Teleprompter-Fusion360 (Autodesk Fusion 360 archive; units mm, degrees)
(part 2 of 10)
sketch "Skizze23" plane through (-14.9969, 0, 0) normal (-1, 0, 0) x axis (0, -1, 0)
  line L1 (18.6596, 263) -> (18.6596, 251.0692)
  line L2 (0.4576, 267) -> (14.6596, 267)
  line L3 (-121.7, 256.955) -> (-0.5298, 266.9593)
  line L4 (-126.9563, 256.521) -> (-123.6681, 256.7925)
  line L5 (-255.037, 12) -> (-136.7133, 249.9055)
  line L6 (-220.3404, 12) -> (-255.037, 12)
  line L7 (-169.9972, 16) -> (-214.6835, 16)
  line L8 (6.6596, 12) -> (-164.3404, 12)
  line L9 (6.6596, 15) -> (6.6596, 12)
  line L10 (-58.0916, 27) -> (-5.3404, 27)
  line L11 (-70.0916, 152.3769) -> (-70.0916, 39)
  line L12 (15.1449, 242.5839) -> (-66.5768, 160.8622)
  line L13 (-45.7711, 251.1832) -> (-86.6874, 247.805)
  line L14 (-77.2147, 189.8223) -> (-36.2984, 230.7386)
  line L15 (-97.7, 235.8456) -> (-97.7, 198.3075)
  line L16 (-94.0916, 39) -> (-94.0916, 104.3769)
  line L17 (-171.4684, 27) -> (-106.0916, 27)
  line L18 (-114.5768, 112.8622) -> (-179.9537, 47.4853)
  line L19 (-156.4445, 183.2864) -> (-195.6625, 104.4333)
  line L20 (-133.7, 138.3075) -> (-133.7, 177.9426)
  line L21 (-176.4327, 90.6042) -> (-137.2147, 129.8223)
  line L22 (-121.7, 244.955) -> (-121.7, 150.455)
  line L23 (-109.7, 244.955) -> (-121.7, 244.955)
  line L24 (-109.7, 150.455) -> (-109.7, 244.955)
  line L25 (-121.7, 150.455) -> (-109.7, 150.455)
  line L26 (-109.7, 213.455) -> (-121.7, 213.455)
  line L27 (-109.7, 181.955) -> (-121.7, 181.955)
  line L28 (-119.5787, 242.8337) -> (-121.7, 244.955)
  line L29 (-113.5498, 244.955) -> (-117.4574, 244.955)
  line L30 (-111.8213, 242.8337) -> (-109.7, 244.955)
  line L31 (-103.0112, 244.955) -> (-109.7, 244.955)
  line L32 (-113.9426, 244.955) -> (-121.7, 244.955)
  line L33 (-109.7, 213.455) -> (-109.7, 240.7124)
  line L34 (-117.4574, 213.455) -> (-109.7, 213.455)
  line L35 (-121.7, 240.7124) -> (-121.7, 213.455)
  line L36 (-119.5787, 215.5763) -> (-121.7, 213.455)
  line L37 (-118.7, 213.455) -> (-121.7, 213.455)
  line L38 (-111.8213, 215.5763) -> (-109.7, 213.455)
  line L39 (-106.7, 213.455) -> (-109.7, 213.455)
  arc A1 centre (6.6596, 251.0692) radius 12 clockwise from (18.6596, 251.0692) to (15.1449, 242.5839)
  arc A2 centre (14.6596, 263) radius 4 clockwise from (14.6596, 267) to (18.6596, 263)
  arc A3 centre (0.4576, 255) radius 12 clockwise from (-0.5298, 266.9593) to (0.4576, 267)
  arc A4 centre (-121.7, 244.955) radius 12 clockwise from (-123.6681, 256.7925) to (-121.7, 256.955)
  arc A5 centre (-125.9689, 244.5617) radius 12 clockwise from (-136.7133, 249.9055) to (-126.9563, 256.521)
  arc A6 centre (-214.6835, 10) radius 6 clockwise from (-220.3404, 12) to (-214.6835, 16)
  arc A7 centre (-169.9972, 10) radius 6 clockwise from (-169.9972, 16) to (-164.3404, 12)
  arc A8 centre (-5.3404, 15) radius 12 clockwise from (-5.3404, 27) to (6.6596, 15)
  arc A9 centre (-58.0916, 39) radius 12 clockwise from (-58.0916, 27) to (-70.0916, 39)
  arc A10 centre (-58.0916, 152.3769) radius 12 clockwise from (-70.0916, 152.3769) to (-66.5768, 160.8622)
  arc A11 centre (-85.7, 235.8456) radius 12 clockwise from (-97.7, 235.8456) to (-86.6874, 247.805)
  arc A12 centre (-44.7837, 239.2239) radius 12 clockwise from (-45.7711, 251.1832) to (-36.2984, 230.7386)
  arc A13 centre (-85.7, 198.3075) radius 12 clockwise from (-77.2147, 189.8223) to (-97.7, 198.3075)
  arc A14 centre (-106.0916, 39) radius 12 clockwise from (-94.0916, 39) to (-106.0916, 27)
  arc A15 centre (-171.4684, 39) radius 12 clockwise from (-171.4684, 27) to (-179.9537, 47.4853)
  arc A16 centre (-106.0916, 104.3769) radius 12 clockwise from (-114.5768, 112.8622) to (-94.0916, 104.3769)
  arc A17 centre (-184.918, 99.0895) radius 12 clockwise from (-176.4327, 90.6042) to (-195.6625, 104.4333)
  arc A18 centre (-145.7, 177.9426) radius 12 clockwise from (-156.4445, 183.2864) to (-133.7, 177.9426)
  arc A19 centre (-145.7, 138.3075) radius 12 clockwise from (-133.7, 138.3075) to (-137.2147, 129.8223)
  arc A20 centre (-119.5787, 242.8337) radius 3 clockwise from (-121.7, 240.7124) to (-117.4574, 244.955)
  arc A21 centre (-111.8213, 242.8337) radius 3 clockwise from (-113.9426, 244.955) to (-109.7, 240.7124)
  arc A22 centre (-119.5787, 215.5763) radius 3 clockwise from (-117.4574, 213.455) to (-121.7, 217.6976)
  arc A23 centre (-111.8213, 215.5763) radius 3 clockwise from (-109.7, 217.6976) to (-113.9426, 213.455)
  arc A24 centre (-119.5787, 179.8337) radius 3 clockwise from (-121.7, 177.7124) to (-117.4574, 181.955)
  arc A25 centre (-111.8213, 179.8337) radius 3 clockwise from (-113.9426, 181.955) to (-109.7, 177.7124)
  arc A26 centre (-111.8213, 152.5763) radius 3 clockwise from (-109.7, 154.6976) to (-113.9426, 150.455)
  arc A27 centre (-119.5787, 152.5763) radius 3 clockwise from (-117.4574, 150.455) to (-121.7, 154.6976)
  point P65 (-121.7, 213.455)
  point P66 (-109.7, 213.455)
  point P67 (-121.7, 181.955)
  point P68 (-109.7, 181.955)
  point P62 (-121.7, 244.955)
  point P69 (-121.7, 244.955)
  point P63 (-109.7, 244.955)
  point P72 (-109.7, 244.955)
  point P70 (-119.5787, 242.8337)
  point P75 (-119.5787, 242.8337)
  point P73 (-111.8213, 242.8337)
  point P76 (-111.8213, 242.8337)
  point P77 (-121.7, 240.7124)
  point P78 (-117.4574, 244.955)
  point P79 (-113.9426, 244.955)
  point P80 (-109.7, 240.7124)
  point P82 (-119.5787, 215.5763)
  point P86 (-119.5787, 215.5763)
  point P84 (-111.8213, 215.5763)
  point P87 (-111.8213, 215.5763)
  point P88 (-117.4574, 213.455)
  point P89 (-121.7, 217.6976)
  point P90 (-109.7, 217.6976)
  point P91 (-113.9426, 213.455)
  coincident L22 P65
  coincident L24 P66
  perpendicular L24 L26
  coincident L22 P67
  coincident L24 P68
  perpendicular L24 L27
  horizontal L29
  coincident P62 P69
  horizontal L31
  coincident P63 P72
  coincident P70 P75
  coincident P62 A20
  coincident P73 P76
  coincident P72 A21
  coincident L22 P77
  coincident L23 P78
  coincident L23 P79
  coincident L24 P80
  horizontal L32
  vertical L33
  horizontal L34
  vertical L35
  horizontal L37
  horizontal L39
  coincident P82 P86
  coincident P65 A22
  coincident P84 P87
  coincident P66 A23
  coincident L26 P88
  coincident L22 P89
  coincident L24 P90
  coincident L26 P91
  dimension "d154" distance L23 L25 = 94.5
  dimension "d155" distance L23 L26 = 31.5 (= "94.50 mm / 3")
  dimension "d156" distance L25 L27 = 31.5 (= "d155")
  dimension "d157" angle L28 L29 = 45
  dimension "d158" angle L30 L31 = 135
  dimension "d159" distance P69 P70 = 3
  dimension "d160" distance P72 P73 = 3
  dimension "d161" angle L36 L37 = 45
  dimension "d162" distance P65 P82 = 3
  dimension "d163" angle L38 L39 = 135
  dimension "d164" distance P66 P84 = 3
extrude "Extrusion21" cut sketch "Skizze23" profile of L22 L23 L24 L25 L26 L27 A20 A21 L32 L33 L34 L35 A22 A23 A24 A25 A26 A27 against normal blind 12
sketch "Skizze24" plane through (-2.9969, 0, 0) normal (-1, 0, 0) x axis (0, -1, 0)
  line L1 (-121.7, 150.455) -> (-121.7, 244.955)
  line L2 (-109.7, 150.455) -> (-121.7, 150.455)
  line L3 (-109.7, 244.955) -> (-109.7, 150.455)
  line L4 (-121.7, 244.955) -> (-109.7, 244.955)
  line L5 (-117.4574, 213.455) -> (-113.9426, 213.455)
  line L6 (-113.9426, 181.955) -> (-117.4574, 181.955)
  line L7 (-109.7, 213.455) -> (-121.7, 213.455)
  line L8 (-109.7, 181.955) -> (-121.7, 181.955)
  line L9 (-109.7, 244.955) -> (-121.7, 244.955)
  line L10 (-109.7, 150.455) -> (-109.7, 244.955)
  line L11 (-121.7, 150.455) -> (-109.7, 150.455)
  line L12 (-121.7, 244.955) -> (-121.7, 150.455)
  line L13 (-57.478, 225.7975) -> (-82.6117, 225.7975)
  line L14 (-57.478, 237.011) -> (-57.478, 225.7975)
  line L15 (-82.6117, 237.011) -> (-57.478, 237.011)
  line L16 (-82.6117, 225.7975) -> (-82.6117, 237.011)
  point P10 (-121.7, 213.455)
  point P11 (-109.7, 213.455)
  point P12 (-121.7, 181.955)
  point P13 (-109.7, 181.955)
  point P4 (-109.7, 150.455)
  point P16 (-109.7, 150.455)
  point P2 (-121.7, 244.955)
  point P14 (-121.7, 244.955)
  coincident L1 P10
  coincident L3 P11
  perpendicular L3 L7
  coincident L1 P12
  coincident L3 P13
  perpendicular L1 L8
  horizontal L9
  vertical L10
  horizontal L11
  vertical L12
  coincident P4 P16
  coincident P2 P14
  horizontal L13
  vertical L14
  horizontal L15
  vertical L16
extrude "Extrusion22" add sketch "Skizze24" profile of L1 L2 L3 L4 L5 L6 L7 L8 L9 L10 L11 L12 along normal blind 12
sketch "Skizze25" plane through (0, 121.7, 0) normal (0, 1, 0) x axis (-1, 0, 0)
  line L1 (-161.0025, 189.955) -> (-161.0025, 194.455)
  line L2 (-141.7525, 189.955) -> (-161.0025, 189.955)
  line L3 (-217.2525, 162.455) -> (-141.7525, 162.455)
  line L4 (-198.0025, 189.955) -> (-217.2525, 189.955)
  line L5 (-198.0025, 194.455) -> (-198.0025, 189.955)
  line L6 (-165.0025, 198.455) -> (-194.0025, 198.455)
  line L7 (-98.617, 174.455) -> (-33.0031, 174.455)
  line L8 (-141.6023, 212.4697) -> (-107.1023, 177.9697)
  line L9 (-33.0031, 232.955) -> (-133.117, 232.955)
  line L10 (-21.0031, 186.455) -> (-21.0031, 220.955)
  line L11 (-338.0031, 220.955) -> (-338.0031, 186.455)
  line L12 (-225.8891, 232.955) -> (-326.0031, 232.955)
  line L13 (-251.9038, 177.9697) -> (-217.4038, 212.4697)
  line L14 (-326.0031, 174.455) -> (-260.3891, 174.455)
  line L15 (14.9969, 150.455) -> (-362.0031, 150.455)
  line L16 (14.9969, 181.955) -> (14.9969, 150.455)
  line L17 (2.9969, 181.955) -> (14.9969, 181.955)
  line L18 (2.9969, 213.455) -> (2.9969, 181.955)
  line L19 (14.9969, 213.455) -> (2.9969, 213.455)
  line L20 (14.9969, 244.955) -> (14.9969, 213.455)
  line L21 (-362.0031, 244.955) -> (14.9969, 244.955)
  line L22 (-362.0031, 150.455) -> (-362.0031, 244.955)
  line L23 (5.1183, 211.3337) -> (2.9969, 213.455)
  line L24 (5.9969, 213.455) -> (2.9969, 213.455)
  line L25 (5.1183, 184.0763) -> (2.9969, 181.955)
  line L26 (5.9969, 181.955) -> (2.9969, 181.955)
  arc A1 centre (-141.7525, 176.205) radius 13.75 clockwise from (-141.7525, 189.955) to (-141.7525, 162.455)
  arc A2 centre (-217.2525, 176.205) radius 13.75 clockwise from (-217.2525, 162.455) to (-217.2525, 189.955)
  arc A3 centre (-194.0025, 194.455) radius 4 clockwise from (-198.0025, 194.455) to (-194.0025, 198.455)
  arc A4 centre (-165.0025, 194.455) radius 4 clockwise from (-165.0025, 198.455) to (-161.0025, 194.455)
  arc A5 centre (-98.617, 186.455) radius 12 clockwise from (-98.617, 174.455) to (-107.1023, 177.9697)
  arc A6 centre (-133.117, 220.955) radius 12 clockwise from (-141.6023, 212.4697) to (-133.117, 232.955)
  arc A7 centre (-33.0031, 220.955) radius 12 clockwise from (-33.0031, 232.955) to (-21.0031, 220.955)
  arc A8 centre (-33.0031, 186.455) radius 12 clockwise from (-21.0031, 186.455) to (-33.0031, 174.455)
  arc A9 centre (-326.0031, 220.955) radius 12 clockwise from (-338.0031, 220.955) to (-326.0031, 232.955)
  arc A10 centre (-225.8891, 220.955) radius 12 clockwise from (-225.8891, 232.955) to (-217.4038, 212.4697)
  arc A11 centre (-260.3891, 186.455) radius 12 clockwise from (-251.9038, 177.9697) to (-260.3891, 174.455)
  arc A12 centre (-326.0031, 186.455) radius 12 clockwise from (-326.0031, 174.455) to (-338.0031, 186.455)
  circle C1 centre (5.1183, 184.0763) radius 3
  circle C2 centre (5.1183, 211.3337) radius 3
  point P44 (2.9969, 213.455)
  point P48 (2.9969, 213.455)
  point P43 (2.9969, 181.955)
  point P51 (2.9969, 181.955)
  point P52 (5.1183, 184.0763)
  point P54 (5.1183, 184.0763)
  point P49 (5.1183, 211.3337)
  point P55 (5.1183, 211.3337)
  horizontal L24
  coincident P44 P48
  horizontal L26
  coincident P43 P51
  coincident P52 P54
  coincident P43 C1
  coincident P49 P55
  coincident P44 C2
  dimension "d169" angle L23 L24 = 45
  dimension "d170" distance P48 P49 = 3
  dimension "d171" angle L25 L26 = 45
  dimension "d172" distance P51 P52 = 3
extrude "Extrusion23" cut sketch "Skizze25" profile of L17 L18 L19 C1 C2 against normal blind 12
work_plane "Arbeitsebene3"
mirror "Spiegeln1" mirrorStitchTolerance 0.1
sketch "Skizze26" plane through (362.0031, 0, 0) normal (1, 0, 0) x axis (0, 1, 0)
  line L1 (121.7, 213.455) -> (109.7, 213.455)
  line L2 (121.7, 244.955) -> (121.7, 213.455)
  line L3 (109.7, 244.955) -> (121.7, 244.955)
  line L4 (109.7, 213.455) -> (109.7, 244.955)
  line L5 (121.7, 213.455) -> (121.7, 244.955)
  line L6 (109.7, 213.455) -> (121.7, 213.455)
  line L7 (109.7, 244.955) -> (109.7, 213.455)
  line L8 (121.7, 244.955) -> (109.7, 244.955)
  line L9 (109.7, 150.455) -> (121.7, 150.455)
  line L10 (109.7, 181.955) -> (109.7, 150.455)
  line L11 (121.7, 181.955) -> (109.7, 181.955)
  line L12 (121.7, 150.455) -> (121.7, 181.955)
extrude "Extrusion24" add sketch "Skizze26" along normal blind 12
sketch "Skizze27" plane through (0, 121.7, 0) normal (0, 1, 0) x axis (-1, 0, 0)
  line L1 (-338.0031, 220.955) -> (-338.0031, 186.455)
  line L2 (-225.8891, 232.955) -> (-326.0031, 232.955)
  line L3 (-251.9038, 177.9697) -> (-217.4038, 212.4697)
  line L4 (-326.0031, 174.455) -> (-260.3891, 174.455)
  line L5 (-98.617, 174.455) -> (-33.0031, 174.455)
  line L6 (-141.6023, 212.4697) -> (-107.1023, 177.9697)
  line L7 (-33.0031, 232.955) -> (-133.117, 232.955)
  line L8 (-21.0031, 186.455) -> (-21.0031, 220.955)
  line L9 (-161.0025, 189.955) -> (-161.0025, 194.455)
  line L10 (-141.7525, 189.955) -> (-161.0025, 189.955)
  line L11 (-217.2525, 162.455) -> (-141.7525, 162.455)
  line L12 (-198.0025, 189.955) -> (-217.2525, 189.955)
  line L13 (-198.0025, 194.455) -> (-198.0025, 189.955)
  line L14 (-165.0025, 198.455) -> (-194.0025, 198.455)
  line L15 (-362.0031, 186.1976) -> (-362.0031, 209.2124)
  line L16 (-374.0031, 181.955) -> (-362.0031, 181.955)
  line L17 (-374.0031, 150.455) -> (-374.0031, 181.955)
  line L18 (14.9969, 150.455) -> (-374.0031, 150.455)
  line L19 (14.9969, 181.955) -> (14.9969, 150.455)
  line L20 (7.2396, 181.955) -> (14.9969, 181.955)
  line L21 (2.9969, 209.2124) -> (2.9969, 186.1976)
  line L22 (14.9969, 213.455) -> (7.2396, 213.455)
  line L23 (14.9969, 244.955) -> (14.9969, 213.455)
  line L24 (-374.0031, 244.955) -> (14.9969, 244.955)
  line L25 (-374.0031, 213.455) -> (-374.0031, 244.955)
  line L26 (-362.0031, 213.455) -> (-374.0031, 213.455)
  arc A1 centre (-326.0031, 220.955) radius 12 clockwise from (-338.0031, 220.955) to (-326.0031, 232.955)
  arc A2 centre (-225.8891, 220.955) radius 12 clockwise from (-225.8891, 232.955) to (-217.4038, 212.4697)
  arc A3 centre (-260.3891, 186.455) radius 12 clockwise from (-251.9038, 177.9697) to (-260.3891, 174.455)
  arc A4 centre (-326.0031, 186.455) radius 12 clockwise from (-326.0031, 174.455) to (-338.0031, 186.455)
  arc A5 centre (-98.617, 186.455) radius 12 clockwise from (-98.617, 174.455) to (-107.1023, 177.9697)
  arc A6 centre (-133.117, 220.955) radius 12 clockwise from (-141.6023, 212.4697) to (-133.117, 232.955)
  arc A7 centre (-33.0031, 220.955) radius 12 clockwise from (-33.0031, 232.955) to (-21.0031, 220.955)
  arc A8 centre (-33.0031, 186.455) radius 12 clockwise from (-21.0031, 186.455) to (-33.0031, 174.455)
  arc A9 centre (-141.7525, 176.205) radius 13.75 clockwise from (-141.7525, 189.955) to (-141.7525, 162.455)
  arc A10 centre (-217.2525, 176.205) radius 13.75 clockwise from (-217.2525, 162.455) to (-217.2525, 189.955)
  arc A11 centre (-194.0025, 194.455) radius 4 clockwise from (-198.0025, 194.455) to (-194.0025, 198.455)
  arc A12 centre (-165.0025, 194.455) radius 4 clockwise from (-165.0025, 198.455) to (-161.0025, 194.455)
  arc A13 centre (-364.1244, 211.3337) radius 3 clockwise from (-362.0031, 213.455) to (-362.0031, 209.2124)
  arc A14 centre (-364.1244, 184.0763) radius 3 clockwise from (-362.0031, 186.1976) to (-362.0031, 181.955)
  arc A15 centre (5.1183, 184.0763) radius 3 clockwise from (7.2396, 181.955) to (2.9969, 186.1976)
  arc A16 centre (5.1183, 211.3337) radius 3 clockwise from (2.9969, 209.2124) to (7.2396, 213.455)
  circle C1 centre (-364.1244, 211.3337) radius 3
  circle C2 centre (-364.1244, 184.0763) radius 3
  point P40 (-362.0031, 209.2124)
  point P41 (-362.0031, 213.455)
  point P43 (-362.0031, 186.1976)
  point P44 (-362.0031, 181.955)
  coincident P40 C1
  coincident P41 C1
  coincident P43 C2
  coincident P44 C2
extrude "Extrusion25" cut sketch "Skizze27" profile of L16 L26 C1 C2 against normal blind 12
offset_faces "Flächen versetzen2" distance 12
sketch "Skizze28" plane through (-14.9969, 0, 0) normal (-1, 0, 0) x axis (0, -1, 0)
  line L1 (-114.5768, 112.8622) -> (-167.9537, 59.4853)
  line L2 (-94.0916, 51) -> (-94.0916, 104.3769)
  line L3 (-159.4684, 39) -> (-106.0916, 39)
  line L4 (-169.9972, 16) -> (-214.6835, 16)
  line L5 (6.6596, 12) -> (-164.3404, 12)
  line L6 (6.6596, 15) -> (6.6596, 12)
  line L7 (-58.0916, 27) -> (-5.3404, 27)
  line L8 (-70.0916, 152.3769) -> (-70.0916, 39)
  line L9 (15.1449, 242.5839) -> (-66.5768, 160.8622)
  line L10 (18.6596, 263) -> (18.6596, 251.0692)
  line L11 (0.4576, 267) -> (14.6596, 267)
  line L12 (-121.7, 256.955) -> (-0.5298, 266.9593)
  line L13 (-126.9563, 256.521) -> (-123.6681, 256.7925)
  line L14 (-255.037, 12) -> (-136.7133, 249.9055)
  line L15 (-220.3404, 12) -> (-255.037, 12)
  line L16 (-121.7, 177.7124) -> (-121.7, 154.6976)
  line L17 (-113.9426, 181.955) -> (-117.4574, 181.955)
  line L18 (-109.7, 154.6976) -> (-109.7, 177.7124)
  line L19 (-117.4574, 150.455) -> (-113.9426, 150.455)
  line L20 (-117.4574, 213.455) -> (-113.9426, 213.455)
  line L21 (-121.7, 240.7124) -> (-121.7, 217.6976)
  line L22 (-113.9426, 244.955) -> (-117.4574, 244.955)
  line L23 (-109.7, 217.6976) -> (-109.7, 240.7124)
  line L24 (-45.7711, 251.1832) -> (-86.6874, 247.805)
  line L25 (-77.2147, 189.8223) -> (-36.2984, 230.7386)
  line L26 (-97.7, 235.8456) -> (-97.7, 198.3075)
  line L27 (-156.4445, 183.2864) -> (-195.6625, 104.4333)
  line L28 (-133.7, 138.3075) -> (-133.7, 177.9426)
  line L29 (-176.4327, 90.6042) -> (-137.2147, 129.8223)
  line L30 (6.6596, 12) -> (6.6596, 0)
  line L31 (-164.3404, 12) -> (6.6596, 12)
  line L32 (-164.3404, 4) -> (-164.3404, 12)
  line L33 (-220.3404, 4) -> (-164.3404, 4)
  line L34 (-220.3404, 12) -> (-220.3404, 4)
  line L35 (-232.4096, 12) -> (-220.3404, 12)
  line L36 (-232.4096, 7.0503) -> (-232.4096, 12)
  line L37 (-240.1877, 7.0503) -> (-232.4096, 7.0503)
  line L38 (-240.1877, 12) -> (-240.1877, 7.0503)
  line L39 (-255.3404, 12) -> (-240.1877, 12)
  line L40 (-255.3404, 0) -> (-255.3404, 12)
  line L41 (6.6596, 0) -> (-255.3404, 0)
  line L42 (-164.3404, 0) -> (-164.3404, 12)
  line L43 (6.6596, 0) -> (6.6596, 12)
  line L44 (-130.1404, 0) -> (-130.1404, 12)
  line L45 (-95.9404, 0) -> (-95.9404, 12)
  line L46 (-61.7404, 0) -> (-61.7404, 12)
  line L47 (-27.5404, 0) -> (-27.5404, 12)
  arc A1 centre (-106.0916, 104.3769) radius 12 clockwise from (-114.5768, 112.8622) to (-94.0916, 104.3769)
  arc A2 centre (-106.0916, 51) radius 12 clockwise from (-94.0916, 51) to (-106.0916, 39)
  arc A3 centre (-159.4684, 51) radius 12 clockwise from (-159.4684, 39) to (-167.9537, 59.4853)
  arc A4 centre (-169.9972, 10) radius 6 clockwise from (-169.9972, 16) to (-164.3404, 12)
  arc A5 centre (-5.3404, 15) radius 12 clockwise from (-5.3404, 27) to (6.6596, 15)
  arc A6 centre (-58.0916, 39) radius 12 clockwise from (-58.0916, 27) to (-70.0916, 39)
  arc A7 centre (-58.0916, 152.3769) radius 12 clockwise from (-70.0916, 152.3769) to (-66.5768, 160.8622)
  arc A8 centre (6.6596, 251.0692) radius 12 clockwise from (18.6596, 251.0692) to (15.1449, 242.5839)
  arc A9 centre (14.6596, 263) radius 4 clockwise from (14.6596, 267) to (18.6596, 263)
  arc A10 centre (0.4576, 255) radius 12 clockwise from (-0.5298, 266.9593) to (0.4576, 267)
  arc A11 centre (-121.7, 244.955) radius 12 clockwise from (-123.6681, 256.7925) to (-121.7, 256.955)
  arc A12 centre (-125.9689, 244.5617) radius 12 clockwise from (-136.7133, 249.9055) to (-126.9563, 256.521)
  arc A13 centre (-214.6835, 10) radius 6 clockwise from (-220.3404, 12) to (-214.6835, 16)
  arc A14 centre (-119.5787, 179.8337) radius 3 clockwise from (-121.7, 177.7124) to (-117.4574, 181.955)
  arc A15 centre (-111.8213, 179.8337) radius 3 clockwise from (-113.9426, 181.955) to (-109.7, 177.7124)
  arc A16 centre (-111.8213, 152.5763) radius 3 clockwise from (-109.7, 154.6976) to (-113.9426, 150.455)
  arc A17 centre (-119.5787, 152.5763) radius 3 clockwise from (-117.4574, 150.455) to (-121.7, 154.6976)
  arc A18 centre (-119.5787, 215.5763) radius 3 clockwise from (-117.4574, 213.455) to (-121.7, 217.6976)
  arc A19 centre (-119.5787, 242.8337) radius 3 clockwise from (-121.7, 240.7124) to (-117.4574, 244.955)
  arc A20 centre (-111.8213, 242.8337) radius 3 clockwise from (-113.9426, 244.955) to (-109.7, 240.7124)
  arc A21 centre (-111.8213, 215.5763) radius 3 clockwise from (-109.7, 217.6976) to (-113.9426, 213.455)
  arc A22 centre (-85.7, 235.8456) radius 12 clockwise from (-97.7, 235.8456) to (-86.6874, 247.805)
  arc A23 centre (-44.7837, 239.2239) radius 12 clockwise from (-45.7711, 251.1832) to (-36.2984, 230.7386)
  arc A24 centre (-85.7, 198.3075) radius 12 clockwise from (-77.2147, 189.8223) to (-97.7, 198.3075)
  arc A25 centre (-184.918, 99.0895) radius 12 clockwise from (-176.4327, 90.6042) to (-195.6625, 104.4333)
  arc A26 centre (-145.7, 177.9426) radius 12 clockwise from (-156.4445, 183.2864) to (-133.7, 177.9426)
  arc A27 centre (-145.7, 138.3075) radius 12 clockwise from (-133.7, 138.3075) to (-137.2147, 129.8223)
  point P87 (-164.3404, 12)
  point P97 (-164.3404, 12)
  point P98 (-164.3404, 0)
  point P86 (6.6596, 12)
  point P99 (6.6596, 12)
  point P85 (6.6596, 0)
  point P100 (6.6596, 0)
  point P101 (-130.1404, 12)
  point P102 (-130.1404, 0)
  point P103 (-95.9404, 12)
  point P104 (-95.9404, 0)
  point P105 (-61.7404, 12)
  point P106 (-61.7404, 0)
  point P107 (-27.5404, 12)
  point P108 (-27.5404, 0)
  coincident P87 P97
  coincident L41 P98
  perpendicular L41 L42
  coincident P86 P99
  coincident P85 P100
  coincident L31 P101
  coincident L41 P102
  perpendicular L41 L44
  coincident L31 P103
  coincident L41 P104
  perpendicular L41 L45
  coincident L31 P105
  coincident L41 P106
  perpendicular L41 L46
  coincident L5 P107
  coincident L41 P108
  perpendicular L41 L47
  dimension "d182" distance L42 L44 = 34.2 (= "( 171 / 5 ) * 1 mm")
  dimension "d183" distance L44 L45 = 34.2 (= "d182")
  dimension "d184" distance L45 L46 = 34.2 (= "d183")
  dimension "d185" distance L46 L47 = 34.2 (= "d184")
  dimension "d186" distance L43 L47 = 34.2
extrude "Extrusion26" add sketch "Skizze28" profile of L5 L30 L31 L32 L41 L42 L43 L44 L45 L46 L47 against normal blind 12
sketch "Skizze29" plane through (-14.9969, 0, 0) normal (-1, 0, 0) x axis (0, -1, 0)
  line L1 (-114.5768, 112.8622) -> (-167.9537, 59.4853)
  line L2 (-94.0916, 51) -> (-94.0916, 104.3769)
  line L3 (-159.4684, 39) -> (-106.0916, 39)
  line L4 (-169.9972, 16) -> (-214.6835, 16)
  line L5 (-164.3404, 0) -> (-164.3404, 12)
  line L6 (-130.1404, 0) -> (-164.3404, 0)
  line L7 (-130.1404, 12) -> (-130.1404, 0)
  line L8 (-95.9404, 12) -> (-130.1404, 12)
  line L9 (-95.9404, 0) -> (-95.9404, 12)
  line L10 (-61.7404, 0) -> (-95.9404, 0)
  line L11 (-61.7404, 12) -> (-61.7404, 0)
  line L12 (-27.5404, 12) -> (-61.7404, 12)
  line L13 (-27.5404, 0) -> (-27.5404, 12)
  line L14 (6.6596, 0) -> (-27.5404, 0)
  line L15 (6.6596, 15) -> (6.6596, 0)
  line L16 (-58.0916, 27) -> (-5.3404, 27)
  line L17 (-70.0916, 152.3769) -> (-70.0916, 39)
  line L18 (15.1449, 242.5839) -> (-66.5768, 160.8622)
  line L19 (18.6596, 263) -> (18.6596, 251.0692)
  line L20 (0.4576, 267) -> (14.6596, 267)
  line L21 (-121.7, 256.955) -> (-0.5298, 266.9593)
  line L22 (-126.9563, 256.521) -> (-123.6681, 256.7925)
  line L23 (-255.037, 12) -> (-136.7133, 249.9055)
  line L24 (-220.3404, 12) -> (-255.037, 12)
  line L25 (-121.7, 177.7124) -> (-121.7, 154.6976)
  line L26 (-113.9426, 181.955) -> (-117.4574, 181.955)
  line L27 (-109.7, 154.6976) -> (-109.7, 177.7124)
  line L28 (-117.4574, 150.455) -> (-113.9426, 150.455)
  line L29 (-117.4574, 213.455) -> (-113.9426, 213.455)
  line L30 (-121.7, 240.7124) -> (-121.7, 217.6976)
  line L31 (-113.9426, 244.955) -> (-117.4574, 244.955)
  line L32 (-109.7, 217.6976) -> (-109.7, 240.7124)
  line L33 (-45.7711, 251.1832) -> (-86.6874, 247.805)
  line L34 (-77.2147, 189.8223) -> (-36.2984, 230.7386)
  line L35 (-97.7, 235.8456) -> (-97.7, 198.3075)
  line L36 (-156.4445, 183.2864) -> (-195.6625, 104.4333)
  line L37 (-133.7, 138.3075) -> (-133.7, 177.9426)
  line L38 (-176.4327, 90.6042) -> (-137.2147, 129.8223)
  line L39 (6.6596, 12) -> (6.6596, 0)
  line L40 (-164.3404, 12) -> (6.6596, 12)
  line L41 (-164.3404, 4) -> (-164.3404, 12)
  line L42 (-220.3404, 4) -> (-164.3404, 4)
  line L43 (-220.3404, 12) -> (-220.3404, 4)
  line L44 (-232.4096, 12) -> (-220.3404, 12)
  line L45 (-232.4096, 7.0503) -> (-232.4096, 12)
  line L46 (-240.1877, 7.0503) -> (-232.4096, 7.0503)
  line L47 (-240.1877, 12) -> (-240.1877, 7.0503)
  line L48 (-255.3404, 12) -> (-240.1877, 12)
  line L49 (-255.3404, 0) -> (-255.3404, 12)
  line L50 (6.6596, 0) -> (-255.3404, 0)
  line L51 (-220.3404, 0) -> (-220.3404, 12)
  line L52 (-220.3404, 12) -> (-240.1877, 12)
  line L53 (-220.3404, 0) -> (-220.3404, 12)
  line L54 (-240.1877, 0) -> (-220.3404, 0)
  line L55 (-240.1877, 12) -> (-240.1877, 0)
  arc A1 centre (-106.0916, 104.3769) radius 12 clockwise from (-114.5768, 112.8622) to (-94.0916, 104.3769)
  arc A2 centre (-106.0916, 51) radius 12 clockwise from (-94.0916, 51) to (-106.0916, 39)
  arc A3 centre (-159.4684, 51) radius 12 clockwise from (-159.4684, 39) to (-167.9537, 59.4853)
  arc A4 centre (-169.9972, 10) radius 6 clockwise from (-169.9972, 16) to (-164.3404, 12)
  arc A5 centre (-5.3404, 15) radius 12 clockwise from (-5.3404, 27) to (6.6596, 15)
  arc A6 centre (-58.0916, 39) radius 12 clockwise from (-58.0916, 27) to (-70.0916, 39)
  arc A7 centre (-58.0916, 152.3769) radius 12 clockwise from (-70.0916, 152.3769) to (-66.5768, 160.8622)
  arc A8 centre (6.6596, 251.0692) radius 12 clockwise from (18.6596, 251.0692) to (15.1449, 242.5839)
  arc A9 centre (14.6596, 263) radius 4 clockwise from (14.6596, 267) to (18.6596, 263)
  arc A10 centre (0.4576, 255) radius 12 clockwise from (-0.5298, 266.9593) to (0.4576, 267)
  arc A11 centre (-121.7, 244.955) radius 12 clockwise from (-123.6681, 256.7925) to (-121.7, 256.955)
  arc A12 centre (-125.9689, 244.5617) radius 12 clockwise from (-136.7133, 249.9055) to (-126.9563, 256.521)
  arc A13 centre (-214.6835, 10) radius 6 clockwise from (-220.3404, 12) to (-214.6835, 16)
  arc A14 centre (-119.5787, 179.8337) radius 3 clockwise from (-121.7, 177.7124) to (-117.4574, 181.955)
  arc A15 centre (-111.8213, 179.8337) radius 3 clockwise from (-113.9426, 181.955) to (-109.7, 177.7124)
  arc A16 centre (-111.8213, 152.5763) radius 3 clockwise from (-109.7, 154.6976) to (-113.9426, 150.455)
  arc A17 centre (-119.5787, 152.5763) radius 3 clockwise from (-117.4574, 150.455) to (-121.7, 154.6976)
  arc A18 centre (-119.5787, 215.5763) radius 3 clockwise from (-117.4574, 213.455) to (-121.7, 217.6976)
  arc A19 centre (-119.5787, 242.8337) radius 3 clockwise from (-121.7, 240.7124) to (-117.4574, 244.955)
  arc A20 centre (-111.8213, 242.8337) radius 3 clockwise from (-113.9426, 244.955) to (-109.7, 240.7124)
  arc A21 centre (-111.8213, 215.5763) radius 3 clockwise from (-109.7, 217.6976) to (-113.9426, 213.455)
  arc A22 centre (-85.7, 235.8456) radius 12 clockwise from (-97.7, 235.8456) to (-86.6874, 247.805)
  arc A23 centre (-44.7837, 239.2239) radius 12 clockwise from (-45.7711, 251.1832) to (-36.2984, 230.7386)
  arc A24 centre (-85.7, 198.3075) radius 12 clockwise from (-77.2147, 189.8223) to (-97.7, 198.3075)
  arc A25 centre (-184.918, 99.0895) radius 12 clockwise from (-176.4327, 90.6042) to (-195.6625, 104.4333)
  arc A26 centre (-145.7, 177.9426) radius 12 clockwise from (-156.4445, 183.2864) to (-133.7, 177.9426)
  arc A27 centre (-145.7, 138.3075) radius 12 clockwise from (-133.7, 138.3075) to (-137.2147, 129.8223)
  point P99 (-220.3404, 12)
  point P106 (-220.3404, 12)
  point P107 (-220.3404, 0)
  point P103 (-240.1877, 12)
  point P108 (-240.1877, 12)
  coincident P99 P106
  coincident L50 P107
  perpendicular L50 L51
  horizontal L52
  vertical L53
  horizontal L54
  vertical L55
  coincident P103 P108
extrude "Extrusion27" add sketch "Skizze29" profile of L24 L43 L44 L45 L46 L47 L50 L51 L52 L53 L54 L55 against normal blind 12
sketch "Skizze30" plane through (-7.3469, 0, 0) normal (1, 0, 0) x axis (0, 1, 0)
  line L1 (-18.6596, 262.7863) -> (-18.6596, 263)
  line L2 (232.1267, 12) -> (-18.6596, 262.7863)
  line L3 (238.3493, 12) -> (232.1267, 12)
  line L4 (-16.2993, 266.6485) -> (238.3493, 12)
  line L5 (242.8632, 1.2635) -> (232.1267, 12)
  line L6 (242.8632, 7.486) -> (238.3493, 12)
  line L7 (242.8632, 1.2635) -> (242.8632, 7.486)
  arc A1 centre (-14.6596, 263) radius 4 clockwise from (-18.6596, 263) to (-16.2993, 266.6485)
  point P6 (232.1267, 12)
  point P8 (232.1267, 12)
  point P7 (238.3493, 12)
  point P9 (238.3493, 12)
  coincident P6 P8
  parallel L2 L5
  coincident P7 P9
  parallel L4 L6
  vertical L7
extrude "Extrusion28" cut sketch "Skizze30" profile of L3 L5 L6 L7 along normal blind 10
sketch "Skizze31" plane through (-14.9969, 0, 0) normal (-1, 0, 0) x axis (0, -1, 0)
  line L1 (-114.5768, 112.8622) -> (-167.9537, 59.4853)
  line L2 (-94.0916, 51) -> (-94.0916, 104.3769)
  line L3 (-159.4684, 39) -> (-106.0916, 39)
  line L4 (-169.9972, 16) -> (-214.6835, 16)
  line L5 (-164.3404, 0) -> (-164.3404, 12)
  line L6 (-130.1404, 0) -> (-164.3404, 0)
  line L7 (-130.1404, 12) -> (-130.1404, 0)
  line L8 (-95.9404, 12) -> (-130.1404, 12)
  line L9 (-95.9404, 0) -> (-95.9404, 12)
  line L10 (-61.7404, 0) -> (-95.9404, 0)
  line L11 (-61.7404, 12) -> (-61.7404, 0)
  line L12 (-27.5404, 12) -> (-61.7404, 12)
  line L13 (-27.5404, 0) -> (-27.5404, 12)
  line L14 (6.6596, 0) -> (-27.5404, 0)
  line L15 (6.6596, 15) -> (6.6596, 0)
  line L16 (-58.0916, 27) -> (-5.3404, 27)
  line L17 (-70.0916, 152.3769) -> (-70.0916, 39)
  line L18 (15.1449, 242.5839) -> (-66.5768, 160.8622)
  line L19 (18.6596, 263) -> (18.6596, 251.0692)
  line L20 (0.4576, 267) -> (14.6596, 267)
  line L21 (-121.7, 256.955) -> (-0.5298, 266.9593)
  line L22 (-126.9563, 256.521) -> (-123.6681, 256.7925)
  line L23 (-255.037, 12) -> (-136.7133, 249.9055)
  line L24 (-240.1877, 12) -> (-255.037, 12)
  line L25 (-240.1877, 0) -> (-240.1877, 12)
  line L26 (-220.3404, 0) -> (-240.1877, 0)
  line L27 (-220.3404, 12) -> (-220.3404, 0)
  line L28 (-121.7, 177.7124) -> (-121.7, 154.6976)
  line L29 (-113.9426, 181.955) -> (-117.4574, 181.955)
  line L30 (-109.7, 154.6976) -> (-109.7, 177.7124)
  line L31 (-117.4574, 150.455) -> (-113.9426, 150.455)
  line L32 (-117.4574, 213.455) -> (-113.9426, 213.455)
  line L33 (-121.7, 240.7124) -> (-121.7, 217.6976)
  line L34 (-113.9426, 244.955) -> (-117.4574, 244.955)
  line L35 (-109.7, 217.6976) -> (-109.7, 240.7124)
  line L36 (-45.7711, 251.1832) -> (-86.6874, 247.805)
  line L37 (-77.2147, 189.8223) -> (-36.2984, 230.7386)
  line L38 (-97.7, 235.8456) -> (-97.7, 198.3075)
  line L39 (-156.4445, 183.2864) -> (-195.6625, 104.4333)
  line L40 (-133.7, 138.3075) -> (-133.7, 177.9426)
  line L41 (-176.4327, 90.6042) -> (-137.2147, 129.8223)
  line L42 (-220.3404, 12) -> (-240.1877, 12)
  line L43 (-220.3404, 6) -> (-240.1877, 6)
  line L44 (-230.2641, 12) -> (-230.2641, 0)
  arc A1 centre (-106.0916, 104.3769) radius 12 clockwise from (-114.5768, 112.8622) to (-94.0916, 104.3769)
  arc A2 centre (-106.0916, 51) radius 12 clockwise from (-94.0916, 51) to (-106.0916, 39)
  arc A3 centre (-159.4684, 51) radius 12 clockwise from (-159.4684, 39) to (-167.9537, 59.4853)
  arc A4 centre (-169.9972, 10) radius 6 clockwise from (-169.9972, 16) to (-164.3404, 12)
  arc A5 centre (-5.3404, 15) radius 12 clockwise from (-5.3404, 27) to (6.6596, 15)
  arc A6 centre (-58.0916, 39) radius 12 clockwise from (-58.0916, 27) to (-70.0916, 39)
  arc A7 centre (-58.0916, 152.3769) radius 12 clockwise from (-70.0916, 152.3769) to (-66.5768, 160.8622)
  arc A8 centre (6.6596, 251.0692) radius 12 clockwise from (18.6596, 251.0692) to (15.1449, 242.5839)
  arc A9 centre (14.6596, 263) radius 4 clockwise from (14.6596, 267) to (18.6596, 263)
  arc A10 centre (0.4576, 255) radius 12 clockwise from (-0.5298, 266.9593) to (0.4576, 267)
  arc A11 centre (-121.7, 244.955) radius 12 clockwise from (-123.6681, 256.7925) to (-121.7, 256.955)
  arc A12 centre (-125.9689, 244.5617) radius 12 clockwise from (-136.7133, 249.9055) to (-126.9563, 256.521)
  arc A13 centre (-214.6835, 10) radius 6 clockwise from (-220.3404, 12) to (-214.6835, 16)
  arc A14 centre (-119.5787, 179.8337) radius 3 clockwise from (-121.7, 177.7124) to (-117.4574, 181.955)
  arc A15 centre (-111.8213, 179.8337) radius 3 clockwise from (-113.9426, 181.955) to (-109.7, 177.7124)
  arc A16 centre (-111.8213, 152.5763) radius 3 clockwise from (-109.7, 154.6976) to (-113.9426, 150.455)
  arc A17 centre (-119.5787, 152.5763) radius 3 clockwise from (-117.4574, 150.455) to (-121.7, 154.6976)
  arc A18 centre (-119.5787, 215.5763) radius 3 clockwise from (-117.4574, 213.455) to (-121.7, 217.6976)
  arc A19 centre (-119.5787, 242.8337) radius 3 clockwise from (-121.7, 240.7124) to (-117.4574, 244.955)
  arc A20 centre (-111.8213, 242.8337) radius 3 clockwise from (-113.9426, 244.955) to (-109.7, 240.7124)
  arc A21 centre (-111.8213, 215.5763) radius 3 clockwise from (-109.7, 217.6976) to (-113.9426, 213.455)
  arc A22 centre (-85.7, 235.8456) radius 12 clockwise from (-97.7, 235.8456) to (-86.6874, 247.805)
  arc A23 centre (-44.7837, 239.2239) radius 12 clockwise from (-45.7711, 251.1832) to (-36.2984, 230.7386)
  arc A24 centre (-85.7, 198.3075) radius 12 clockwise from (-77.2147, 189.8223) to (-97.7, 198.3075)
  arc A25 centre (-184.918, 99.0895) radius 12 clockwise from (-176.4327, 90.6042) to (-195.6625, 104.4333)
  arc A26 centre (-145.7, 177.9426) radius 12 clockwise from (-156.4445, 183.2864) to (-133.7, 177.9426)
  arc A27 centre (-145.7, 138.3075) radius 12 clockwise from (-133.7, 138.3075) to (-137.2147, 129.8223)
  circle C1 centre (-230.2641, 6) radius 1.5
  point P50 (-240.1877, 12)
  point P97 (-240.1877, 12)
  point P53 (-220.3404, 12)
  point P98 (-220.3404, 12)
  point P99 (-240.1877, 6)
  point P100 (-220.3404, 6)
  point P101 (-230.2641, 0)
  point P102 (-230.2641, 12)
  point P103 (-230.2641, 6)
  coincident P50 P97
  coincident P53 P98
  midpoint L25 P99
  midpoint L27 P100
  midpoint L26 P101
  midpoint L42 P102
  midpoint L44 P103
  dimension "d193" diameter C1 = 3
extrude "Extrusion29" cut sketch "Skizze31" profile of C1 against normal blind 17
sketch "Skizze32" plane through (-14.9969, 0, 0) normal (-1, 0, 0) x axis (0, -1, 0)
  line L1 (-114.5768, 112.8622) -> (-167.9537, 59.4853)
  line L2 (-94.0916, 51) -> (-94.0916, 104.3769)
  line L3 (-159.4684, 39) -> (-106.0916, 39)
  line L4 (-169.9972, 16) -> (-214.6835, 16)
  line L5 (-164.3404, 0) -> (-164.3404, 12)
  line L6 (-130.1404, 0) -> (-164.3404, 0)
  line L7 (-130.1404, 12) -> (-130.1404, 0)
  line L8 (-95.9404, 12) -> (-130.1404, 12)
  line L9 (-95.9404, 0) -> (-95.9404, 12)
  line L10 (-61.7404, 0) -> (-95.9404, 0)
  line L11 (-61.7404, 12) -> (-61.7404, 0)
  line L12 (-27.5404, 12) -> (-61.7404, 12)
  line L13 (-27.5404, 0) -> (-27.5404, 12)
  line L14 (6.6596, 0) -> (-27.5404, 0)
  line L15 (6.6596, 15) -> (6.6596, 0)
  line L16 (-58.0916, 27) -> (-5.3404, 27)
  line L17 (-70.0916, 152.3769) -> (-70.0916, 39)
  line L18 (15.1449, 242.5839) -> (-66.5768, 160.8622)
  line L19 (18.6596, 263) -> (18.6596, 251.0692)
  line L20 (0.4576, 267) -> (14.6596, 267)
  line L21 (-121.7, 256.955) -> (-0.5298, 266.9593)
  line L22 (-126.9563, 256.521) -> (-123.6681, 256.7925)
  line L23 (-255.037, 12) -> (-136.7133, 249.9055)
  line L24 (-240.1877, 12) -> (-255.037, 12)
  line L25 (-240.1877, 0) -> (-240.1877, 12)
  line L26 (-220.3404, 0) -> (-240.1877, 0)
  line L27 (-220.3404, 12) -> (-220.3404, 0)
  line L28 (-121.7, 177.7124) -> (-121.7, 154.6976)
  line L29 (-113.9426, 181.955) -> (-117.4574, 181.955)
  line L30 (-109.7, 154.6976) -> (-109.7, 177.7124)
  line L31 (-117.4574, 150.455) -> (-113.9426, 150.455)
  line L32 (-117.4574, 213.455) -> (-113.9426, 213.455)
  line L33 (-121.7, 240.7124) -> (-121.7, 217.6976)
  line L34 (-113.9426, 244.955) -> (-117.4574, 244.955)
  line L35 (-109.7, 217.6976) -> (-109.7, 240.7124)
  line L36 (-45.7711, 251.1832) -> (-86.6874, 247.805)
  line L37 (-77.2147, 189.8223) -> (-36.2984, 230.7386)
  line L38 (-97.7, 235.8456) -> (-97.7, 198.3075)
  line L39 (-156.4445, 183.2864) -> (-195.6625, 104.4333)
  line L40 (-133.7, 138.3075) -> (-133.7, 177.9426)
  line L41 (-176.4327, 90.6042) -> (-137.2147, 129.8223)
  line L42 (-185.2816, 12) -> (6.6596, 12)
  line L43 (-130.1404, 12) -> (-164.3404, 0)
  line L44 (-95.9404, 0) -> (-61.7404, 12)
  line L45 (6.6596, 12) -> (-27.5404, 0)
  line L46 (-27.5404, 12) -> (6.6596, 0)
  line L47 (-95.9404, 12) -> (-61.7404, 0)
  line L48 (-164.3404, 12) -> (-130.1404, 0)
  circle C1 centre (-230.2641, 6) radius 1.5
  arc A1 centre (-106.0916, 104.3769) radius 12 clockwise from (-114.5768, 112.8622) to (-94.0916, 104.3769)
  arc A2 centre (-106.0916, 51) radius 12 clockwise from (-94.0916, 51) to (-106.0916, 39)
  arc A3 centre (-159.4684, 51) radius 12 clockwise from (-159.4684, 39) to (-167.9537, 59.4853)
  arc A4 centre (-169.9972, 10) radius 6 clockwise from (-169.9972, 16) to (-164.3404, 12)
  arc A5 centre (-5.3404, 15) radius 12 clockwise from (-5.3404, 27) to (6.6596, 15)
  arc A6 centre (-58.0916, 39) radius 12 clockwise from (-58.0916, 27) to (-70.0916, 39)
  arc A7 centre (-58.0916, 152.3769) radius 12 clockwise from (-70.0916, 152.3769) to (-66.5768, 160.8622)
  arc A8 centre (6.6596, 251.0692) radius 12 clockwise from (18.6596, 251.0692) to (15.1449, 242.5839)
  arc A9 centre (14.6596, 263) radius 4 clockwise from (14.6596, 267) to (18.6596, 263)
  arc A10 centre (0.4576, 255) radius 12 clockwise from (-0.5298, 266.9593) to (0.4576, 267)
  arc A11 centre (-121.7, 244.955) radius 12 clockwise from (-123.6681, 256.7925) to (-121.7, 256.955)
  arc A12 centre (-125.9689, 244.5617) radius 12 clockwise from (-136.7133, 249.9055) to (-126.9563, 256.521)
  arc A13 centre (-214.6835, 10) radius 6 clockwise from (-220.3404, 12) to (-214.6835, 16)
  arc A14 centre (-119.5787, 179.8337) radius 3 clockwise from (-121.7, 177.7124) to (-117.4574, 181.955)
  arc A15 centre (-111.8213, 179.8337) radius 3 clockwise from (-113.9426, 181.955) to (-109.7, 177.7124)
  arc A16 centre (-111.8213, 152.5763) radius 3 clockwise from (-109.7, 154.6976) to (-113.9426, 150.455)
  arc A17 centre (-119.5787, 152.5763) radius 3 clockwise from (-117.4574, 150.455) to (-121.7, 154.6976)
  arc A18 centre (-119.5787, 215.5763) radius 3 clockwise from (-117.4574, 213.455) to (-121.7, 217.6976)
  arc A19 centre (-119.5787, 242.8337) radius 3 clockwise from (-121.7, 240.7124) to (-117.4574, 244.955)
  arc A20 centre (-111.8213, 242.8337) radius 3 clockwise from (-113.9426, 244.955) to (-109.7, 240.7124)
  arc A21 centre (-111.8213, 215.5763) radius 3 clockwise from (-109.7, 217.6976) to (-113.9426, 213.455)
  arc A22 centre (-85.7, 235.8456) radius 12 clockwise from (-97.7, 235.8456) to (-86.6874, 247.805)
  arc A23 centre (-44.7837, 239.2239) radius 12 clockwise from (-45.7711, 251.1832) to (-36.2984, 230.7386)
  arc A24 centre (-85.7, 198.3075) radius 12 clockwise from (-77.2147, 189.8223) to (-97.7, 198.3075)
  arc A25 centre (-184.918, 99.0895) radius 12 clockwise from (-176.4327, 90.6042) to (-195.6625, 104.4333)
  arc A26 centre (-145.7, 177.9426) radius 12 clockwise from (-156.4445, 183.2864) to (-133.7, 177.9426)
  arc A27 centre (-145.7, 138.3075) radius 12 clockwise from (-133.7, 138.3075) to (-137.2147, 129.8223)
  circle C2 centre (-147.2404, 6) radius 1.5
  circle C3 centre (-78.8404, 6) radius 1.5
  circle C4 centre (-10.4404, 6) radius 1.5
  point P19 (-95.9404, 12)
  point P22 (-61.7404, 12)
  point P99 (6.6596, 12)
  point P23 (-27.5404, 12)
  point P16 (-164.3404, 0)
  point P100 (-164.3404, 0)
  point P18 (-130.1404, 12)
  point P101 (-130.1404, 12)
  point P102 (-61.7404, 12)
  point P20 (-95.9404, 0)
  point P103 (-95.9404, 0)
  point P24 (-27.5404, 0)
  point P104 (-27.5404, 0)
  point P25 (6.6596, 0)
  point P105 (6.6596, 0)
  point P106 (-27.5404, 12)
  point P21 (-61.7404, 0)
  point P107 (-61.7404, 0)
  point P108 (-95.9404, 12)
  point P17 (-130.1404, 0)
  point P109 (-130.1404, 0)
  point P14 (-164.3404, 12)
  point P110 (-164.3404, 12)
  point P111 (-147.2404, 6)
  point P112 (-78.8404, 6)
  point P113 (-10.4404, 6)
  perpendicular L5 L42
  coincident P19 L42
  coincident P22 L42
  coincident L15 P99
  coincident P23 L42
  coincident P16 P100
  coincident P18 P101
  coincident P22 P102
  coincident P20 P103
  coincident P24 P104
  coincident P25 P105
  coincident P23 P106
  coincident P21 P107
  coincident P19 P108
  coincident P17 P109
  coincident P14 P110
  midpoint L48 P111
  midpoint L47 P112
  midpoint L46 P113
  dimension "d196" diameter C2 = 3
  dimension "d197" diameter C3 = 3
  dimension "d198" diameter C4 = 3
extrude "Extrusion30" cut sketch "Skizze32" profile of C2 C3 C4 against normal blind 25
sketch "Skizze34" plane through (0, 0, 12) normal (0, 0, 1) x axis (-1, 0, 0)
  line L1 (-374.0031, -168.3404) -> (-374.0031, 6.6596)
  line L2 (-364.0031, -168.3404) -> (-374.0031, -168.3404)
  line L3 (-360.0031, 0.1596) -> (-360.0031, -169.8683)
  line L4 (-3.5031, 4.6596) -> (-355.5031, 4.6596)
  line L5 (0.9969, -164.3404) -> (0.9969, 0.1596)
  line L6 (14.9969, -164.3404) -> (0.9969, -164.3404)
  line L7 (14.9969, 6.6596) -> (14.9969, -164.3404)
  line L8 (-362.0031, 18.6596) -> (2.9969, 18.6596)
  line L9 (-3.5031, -226.3404) -> (-355.5031, -226.3404)
  line L10 (0.9969, -220.3404) -> (0.9969, -221.8404)
  line L11 (14.9969, -220.3404) -> (0.9969, -220.3404)
  line L12 (14.9969, -164.3404) -> (14.9969, -220.3404)
  line L13 (0.9969, -164.3404) -> (14.9969, -164.3404)
  line L14 (0.9969, -150.3404) -> (0.9969, -164.3404)
  line L15 (-360.0031, -150.3404) -> (0.9969, -150.3404)
  line L16 (-360.0031, -169.8683) -> (-360.0031, -150.3404)
  line L17 (-358.0031, -212.3404) -> (-358.0031, -174.3404)
  line L18 (-360.0031, -221.8404) -> (-360.0031, -216.8125)
  line L19 (-300.0031, -174.3404) -> (-300.0031, -190.3404)
  line L20 (-203.5031, -162.3404) -> (-288.0031, -162.3404)
  line L21 (-191.5031, -190.3404) -> (-191.5031, -174.3404)
  line L22 (-288.0031, -202.3404) -> (-203.5031, -202.3404)
  line L23 (-155.5031, -202.3404) -> (-71.0031, -202.3404)
  line L24 (-167.5031, -174.3404) -> (-167.5031, -190.3404)
  line L25 (-71.0031, -162.3404) -> (-155.5031, -162.3404)
  line L26 (-59.0031, -190.3404) -> (-59.0031, -174.3404)
  line L27 (-1.1244, -152.4617) -> (0.9969, -150.3404)
  line L28 (3.9969, -150.3404) -> (0.9969, -150.3404)
  line L29 (-357.8817, -152.4617) -> (-360.0031, -150.3404)
  line L30 (-357.0031, -150.3404) -> (-360.0031, -150.3404)
  arc A1 centre (-362.0031, 6.6596) radius 12 clockwise from (-374.0031, 6.6596) to (-362.0031, 18.6596)
  arc A2 centre (-364.0031, -174.3404) radius 6 clockwise from (-364.0031, -168.3404) to (-360.0031, -169.8683)
  arc A3 centre (-355.5031, 0.1596) radius 4.5 clockwise from (-360.0031, 0.1596) to (-355.5031, 4.6596)
  arc A4 centre (-3.5031, 0.1596) radius 4.5 clockwise from (-3.5031, 4.6596) to (0.9969, 0.1596)
  arc A5 centre (2.9969, 6.6596) radius 12 clockwise from (2.9969, 18.6596) to (14.9969, 6.6596)
  arc A6 centre (-355.5031, -221.8404) radius 4.5 clockwise from (-355.5031, -226.3404) to (-360.0031, -221.8404)
  arc A7 centre (-3.5031, -221.8404) radius 4.5 clockwise from (0.9969, -221.8404) to (-3.5031, -226.3404)
  arc A8 centre (-364.0031, -174.3404) radius 6 clockwise from (-360.0031, -169.8683) to (-358.0031, -174.3404)
  arc A9 centre (-364.0031, -212.3404) radius 6 clockwise from (-358.0031, -212.3404) to (-360.0031, -216.8125)
  arc A10 centre (-288.0031, -174.3404) radius 12 clockwise from (-300.0031, -174.3404) to (-288.0031, -162.3404)
  arc A11 centre (-203.5031, -174.3404) radius 12 clockwise from (-203.5031, -162.3404) to (-191.5031, -174.3404)
  arc A12 centre (-203.5031, -190.3404) radius 12 clockwise from (-191.5031, -190.3404) to (-203.5031, -202.3404)
  arc A13 centre (-288.0031, -190.3404) radius 12 clockwise from (-288.0031, -202.3404) to (-300.0031, -190.3404)
  arc A14 centre (-155.5031, -190.3404) radius 12 clockwise from (-155.5031, -202.3404) to (-167.5031, -190.3404)
  arc A15 centre (-155.5031, -174.3404) radius 12 clockwise from (-167.5031, -174.3404) to (-155.5031, -162.3404)
  arc A16 centre (-71.0031, -174.3404) radius 12 clockwise from (-71.0031, -162.3404) to (-59.0031, -174.3404)
  arc A17 centre (-71.0031, -190.3404) radius 12 clockwise from (-59.0031, -190.3404) to (-71.0031, -202.3404)
  circle C1 centre (-357.8817, -152.4617) radius 3
  circle C2 centre (-1.1244, -152.4617) radius 3
  point P30 (0.9969, -150.3404)
  point P62 (0.9969, -150.3404)
  point P31 (-360.0031, -150.3404)
  point P65 (-360.0031, -150.3404)
  point P66 (-357.8817, -152.4617)
  point P68 (-357.8817, -152.4617)
  point P63 (-1.1244, -152.4617)
  point P69 (-1.1244, -152.4617)
  horizontal L28
  coincident P30 P62
  horizontal L30
  coincident P31 P65
  coincident P66 P68
  coincident P65 C1
  coincident P63 P69
  coincident P30 C2
  dimension "d201" angle L27 L28 = 135
  dimension "d202" distance P62 P63 = 3
  dimension "d203" angle L29 L30 = 45
  dimension "d204" distance P65 P66 = 3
